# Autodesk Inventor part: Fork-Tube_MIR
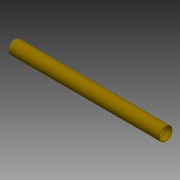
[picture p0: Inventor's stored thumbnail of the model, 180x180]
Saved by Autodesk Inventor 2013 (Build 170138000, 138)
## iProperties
Created: 2001-11
Part Number: Fork-Tube_MIR
Document SubType Name: Modeling
Designer: Autodesk, Inc.
Mass: 63.0746 g
Surface Area: 510.582 cm^2
Volume: 63.0746 cm^3
Density: 1 g/cm^3
Material: Generic
Author: Autodesk, Inc.
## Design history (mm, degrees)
derived "Fork-Tube.ipt"
body "Solid1"
tag "TaggingFeature2"
feature "DerivedBody::Fork-Tube.ipt" dims "d0" = 10
